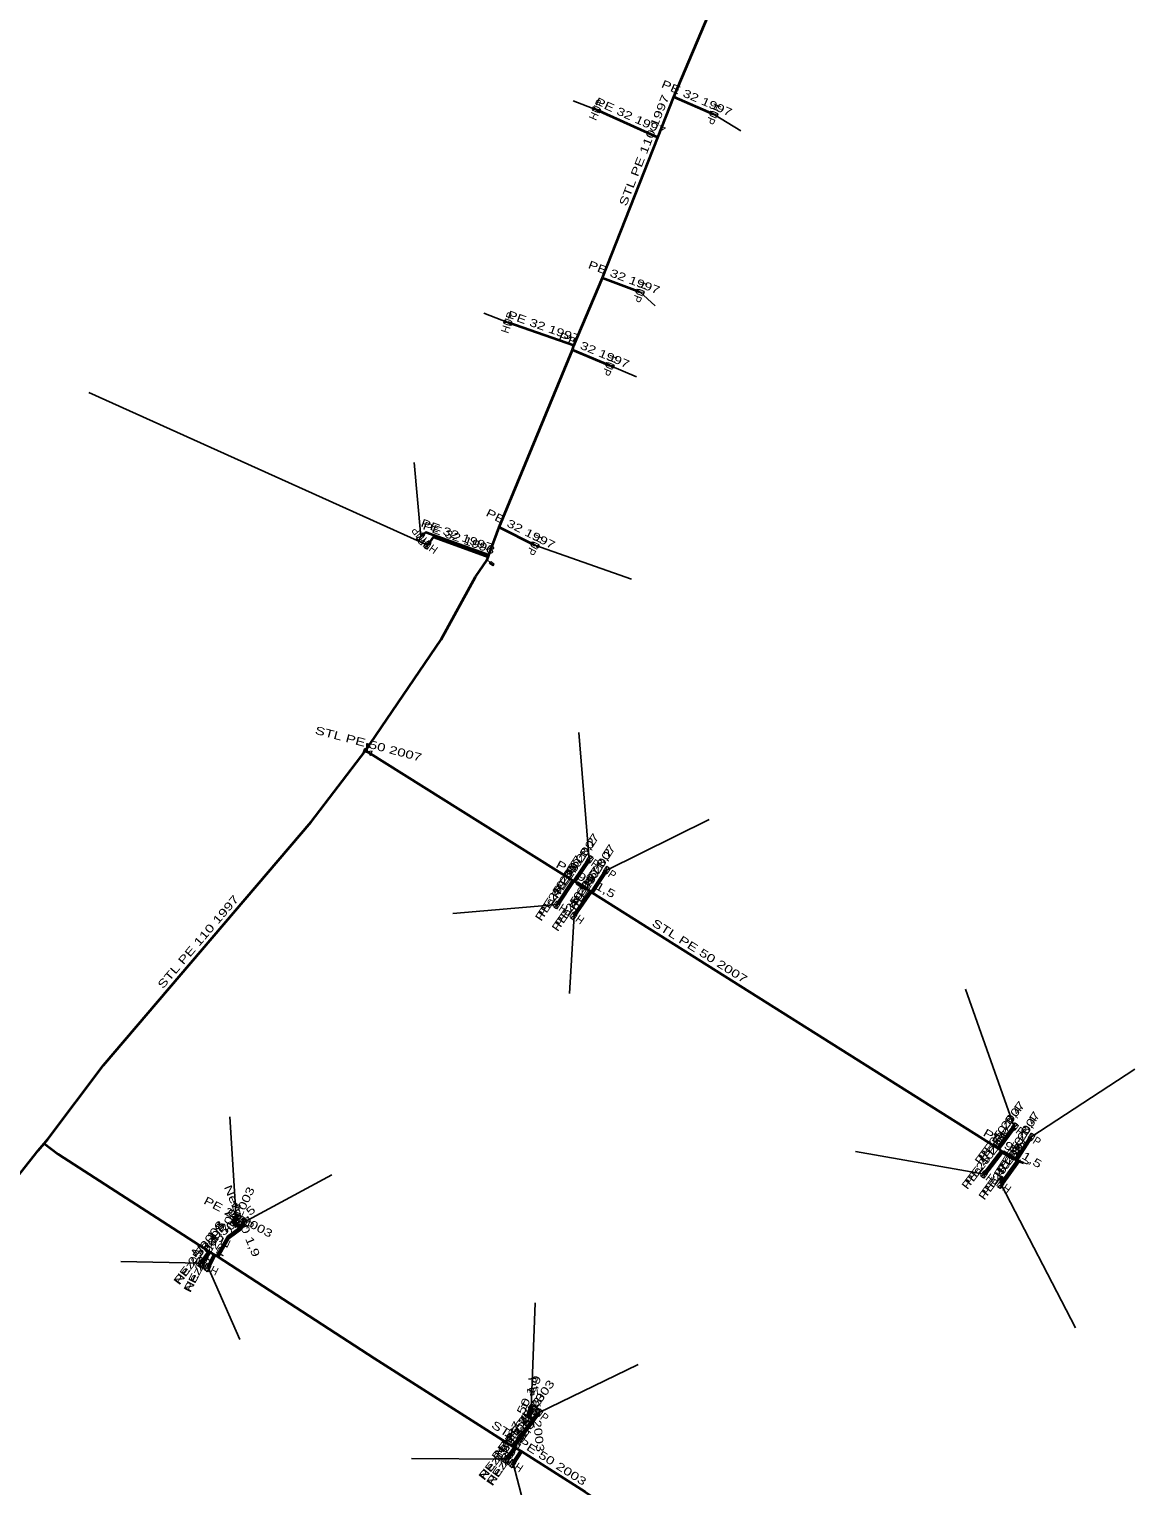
# Model space of a CAD drawing. Extents: x -737484 to -734496, y -1033882 to -1030666.
# Drawn here: x -736166.9 to -736028.6, y -1032786.1 to -1032604 of the extents above; entities that cross this region are included whole.
import ezdxf
from ezdxf.enums import TextEntityAlignment as Align

# ---------------------------------------------------------------- set-up
doc = ezdxf.new("R2010")
doc.units = 0
doc.header["$LTSCALE"] = 0.4
for name, color, linetype, lineweight in [('1', 7, 'Continuous', 13), ('18', 7, 'Continuous', 60), ('22', 7, 'Continuous', 25), ('5', 7, 'Continuous', 35), ('7', 7, 'Continuous', 35)]:
    doc.layers.add(name, color=color, linetype=linetype, lineweight=lineweight)
doc.layers.add('2', color=7, linetype='Continuous')

msp = doc.modelspace()

# ---------------------------------------------------------------- linework, layer by layer
at = {"layer": '1'}
for p, q in [((-736109.567, -1032670.34), (-736109.178, -1032670.654)), ((-736109.167, -1032670.76), (-736108.895, -1032670.98)), ((-736124.522, -1032694.331), (-736124.522, -1032693.831)), ((-736124.447, -1032693.756), (-736124.447, -1032693.406)), ((-736045.29, -1032748.4), (-736045.29, -1032747.9)), ((-736045.215, -1032747.825), (-736045.215, -1032747.475))]:
    msp.add_line(p, q, dxfattribs=at)
for points in [[(-736096.417, -1032614.046), (-736096.254, -1032613.68), (-736095.503, -1032614.453), (-736095.34, -1032614.087)], [(-736080.709, -1032614.621), (-736080.865, -1032614.989), (-736081.63, -1032614.23), (-736081.786, -1032614.598)], [(-736089.92, -1032636.839), (-736090.063, -1032637.212), (-736090.854, -1032636.481), (-736090.997, -1032636.854)], [(-736107.505, -1032640.703), (-736107.375, -1032640.325), (-736106.56, -1032641.028), (-736106.43, -1032640.65)], [(-736093.71, -1032646.04), (-736093.866, -1032646.408), (-736094.631, -1032645.649), (-736094.787, -1032646.017)], [(-736118.144, -1032667.894), (-736118.401, -1032667.588), (-736117.378, -1032667.251), (-736117.635, -1032666.945)], [(-736117.142, -1032669.008), (-736117.47, -1032668.778), (-736116.569, -1032668.189), (-736116.897, -1032667.959)], [(-736103.071, -1032668.526), (-736103.253, -1032668.883), (-736103.962, -1032668.072), (-736104.144, -1032668.429)], [(-736108.789, -1032670.969), (-736108.884, -1032671.085), (-736109.272, -1032670.771), (-736109.178, -1032670.654)], [(-736108.842, -1032670.974), (-736108.889, -1032671.032), (-736109.22, -1032670.764), (-736109.172, -1032670.706)], [(-736108.789, -1032670.969), (-736108.695, -1032670.852), (-736109.084, -1032670.538), (-736109.178, -1032670.654)], [(-736125.1, -1032694.406), (-736124.86, -1032693.856), (-736124.183, -1032694.805), (-736123.943, -1032694.255)], [(-736124.522, -1032693.331), (-736124.672, -1032693.331), (-736124.672, -1032693.831), (-736124.522, -1032693.831)], [(-736124.522, -1032693.331), (-736124.372, -1032693.331), (-736124.372, -1032693.831), (-736124.522, -1032693.831)], [(-736124.485, -1032693.369), (-736124.41, -1032693.369), (-736124.41, -1032693.794), (-736124.485, -1032693.794)], [(-736096.701, -1032707.276), (-736096.369, -1032707.5), (-736097.26, -1032708.105), (-736096.928, -1032708.329)], [(-736094.591, -1032708.635), (-736094.255, -1032708.853), (-736095.136, -1032709.474), (-736094.8, -1032709.692)], [(-736100.895, -1032713.952), (-736101.231, -1032713.734), (-736100.35, -1032713.113), (-736100.686, -1032712.895)], [(-736098.815, -1032715.309), (-736099.143, -1032715.079), (-736098.242, -1032714.49), (-736098.57, -1032714.26)], [(-736043.516, -1032740.693), (-736043.197, -1032740.934), (-736044.118, -1032741.491), (-736043.799, -1032741.732)], [(-736041.483, -1032741.979), (-736041.144, -1032742.191), (-736042.013, -1032742.828), (-736041.674, -1032743.04)], [(-736047.496, -1032747.626), (-736047.815, -1032747.385), (-736046.894, -1032746.828), (-736047.213, -1032746.587)], [(-736045.422, -1032748.922), (-736045.745, -1032748.686), (-736044.834, -1032748.113), (-736045.157, -1032747.877)], [(-736045.29, -1032747.4), (-736045.44, -1032747.4), (-736045.44, -1032747.9), (-736045.29, -1032747.9)], [(-736045.29, -1032747.4), (-736045.14, -1032747.4), (-736045.14, -1032747.9), (-736045.29, -1032747.9)], [(-736045.253, -1032747.438), (-736045.178, -1032747.438), (-736045.178, -1032747.863), (-736045.253, -1032747.863)], [(-736140.814, -1032752.067), (-736140.499, -1032752.314), (-736141.43, -1032752.855), (-736141.115, -1032753.102)], [(-736140.005, -1032752.641), (-736139.643, -1032752.81), (-736140.428, -1032753.547), (-736140.066, -1032753.716)], [(-736145.498, -1032758.762), (-736145.817, -1032758.521), (-736144.896, -1032757.964), (-736145.215, -1032757.723)], [(-736144.529, -1032759.32), (-736144.886, -1032759.138), (-736144.075, -1032758.429), (-736144.432, -1032758.247)], [(-736103.975, -1032775.863), (-736103.628, -1032776.063), (-736104.475, -1032776.73), (-736104.128, -1032776.93)], [(-736103.005, -1032776.448), (-736102.682, -1032776.684), (-736103.593, -1032777.257), (-736103.27, -1032777.493)], [(-736107.324, -1032783.257), (-736107.639, -1032783.01), (-736106.708, -1032782.469), (-736107.023, -1032782.222)], [(-736106.453, -1032783.807), (-736106.785, -1032783.583), (-736105.894, -1032782.978), (-736106.226, -1032782.754)]]:
    msp.add_lwpolyline(points, close=True, dxfattribs=at)
msp.add_lwpolyline([(-736041.927, -1032745.636), (-736042.013, -1032745.871), (-736042.952, -1032745.528), (-736042.867, -1032745.294)], dxfattribs=at)
at = {"layer": '18'}
for p, q in [((-736098.655, -1032710.503), (-736096.815, -1032707.803)), ((-736098.816, -1032710.434), (-736100.791, -1032713.424)), ((-736096.462, -1032711.924), (-736094.696, -1032709.164)), ((-736096.615, -1032711.8), (-736098.693, -1032714.785)), ((-736045.656, -1032743.897), (-736043.658, -1032741.213)), ((-736043.392, -1032745.363), (-736041.579, -1032742.51)), ((-736045.173, -1032744.258), (-736047.355, -1032747.107)), ((-736043.147, -1032745.463), (-736045.29, -1032748.4)), ((-736045.024, -1032744.371), (-736043.707, -1032745.15)), ((-736144.294, -1032756.819), (-736145.356, -1032758.242)), ((-736143.662, -1032757.2), (-736144.481, -1032758.783)), ((-736106.323, -1032781.2), (-736103.137, -1032776.97)), ((-736106.053, -1032781.317), (-736107.173, -1032782.741)), ((-736105.3, -1032781.761), (-736106.339, -1032783.28))]:
    msp.add_line(p, q, dxfattribs=at)
for points in [[(-736098.356, -1032710.709), (-736097.739, -1032711.112), (-736097.057, -1032711.486)], [(-736140.328, -1032753.795), (-736141.137, -1032753.383), (-736141.296, -1032752.997), (-736140.936, -1032752.548)], [(-736143.284, -1032757.398), (-736141.977, -1032755.055), (-736140.402, -1032753.86), (-736140.035, -1032753.179)], [(-736103.801, -1032777.768), (-736104.298, -1032777.483), (-736104.414, -1032777.134), (-736103.982, -1032776.254)]]:
    msp.add_lwpolyline(points, dxfattribs=at)
at = {"layer": '22'}
for p, q in [((-736095.879, -1032614.068), (-736098.835, -1032612.937)), ((-736081.249, -1032614.61), (-736077.847, -1032616.722)), ((-736090.459, -1032636.848), (-736088.549, -1032638.576)), ((-736106.969, -1032640.678), (-736109.996, -1032639.493)), ((-736094.25, -1032646.029), (-736090.914, -1032647.448)), ((-736117.02, -1032668.484), (-736159.393, -1032649.411)), ((-736117.89, -1032667.42), (-736118.694, -1032658.15)), ((-736103.609, -1032668.479), (-736091.505, -1032672.733)), ((-736096.815, -1032707.803), (-736098.127, -1032691.919)), ((-736094.696, -1032709.164), (-736081.81, -1032702.797)), ((-736100.791, -1032713.424), (-736113.871, -1032714.534)), ((-736098.693, -1032714.785), (-736099.272, -1032724.553)), ((-736043.658, -1032741.213), (-736049.748, -1032723.98)), ((-736041.579, -1032742.51), (-736028.564, -1032734)), ((-736140.965, -1032752.585), (-736141.74, -1032739.974)), ((-736047.355, -1032747.107), (-736063.489, -1032744.305)), ((-736140.036, -1032753.179), (-736128.99, -1032747.189)), ((-736045.29, -1032748.4), (-736036.007, -1032766.348)), ((-736145.357, -1032758.243), (-736155.38, -1032758.046)), ((-736144.481, -1032758.784), (-736140.494, -1032767.779)), ((-736104.052, -1032776.397), (-736103.566, -1032763.199)), ((-736103.138, -1032776.971), (-736090.684, -1032770.928)), ((-736107.174, -1032782.74), (-736119.024, -1032782.665)), ((-736106.34, -1032783.281), (-736103.566, -1032793.829))]:
    msp.add_line(p, q, dxfattribs=at)
at = {"layer": '5'}
msp.add_line((-736124.815, -1032694.254), (-736124.522, -1032694.331), dxfattribs=at)
for points in [[(-736124.815, -1032694.254), (-736115.32, -1032680.29), (-736111.02, -1032672.47), (-736109.57, -1032670.34), (-736109.44, -1032669.98), (-736109.36, -1032669.76), (-736108.07, -1032666.23), (-736098.91, -1032644.08), (-736098.72, -1032643.55), (-736095.14, -1032635.08), (-736088.23, -1032617.52), (-736086.24, -1032612.47), (-736081.39, -1032601.03), (-736081.15, -1032600.32), (-736076.37, -1032589.26), (-736075.69, -1032587.6), (-736070.52, -1032575.85), (-736066.71, -1032567.15), (-736058.44, -1032548.57), (-736056.26, -1032543.42), (-736056.11, -1032543.06)], [(-736164.978, -1032743.294), (-736164.512, -1032742.749), (-736157.56, -1032733.51), (-736131.6, -1032703.07), (-736124.815, -1032694.254)], [(-736124.522, -1032694.331), (-736098.816, -1032710.434), (-736098.655, -1032710.503), (-736098.356, -1032710.709), (-736097.739, -1032711.112), (-736097.057, -1032711.486), (-736096.615, -1032711.8), (-736096.462, -1032711.924), (-736045.656, -1032743.897), (-736045.173, -1032744.258), (-736045.024, -1032744.371), (-736043.707, -1032745.15), (-736043.392, -1032745.363), (-736043.147, -1032745.463), (-736042.483, -1032745.7)], [(-736210.44, -1032798.17), (-736209.51, -1032797.02), (-736177.54, -1032759.07), (-736165.735, -1032744.144), (-736164.978, -1032743.294)], [(-736164.978, -1032743.294), (-736163.22, -1032744.622), (-736144.295, -1032756.82), (-736143.663, -1032757.201), (-736143.285, -1032757.399), (-736123.669, -1032770.149), (-736106.324, -1032781.201), (-736106.054, -1032781.318), (-736105.301, -1032781.762), (-736097.333, -1032786.842), (-736084.708, -1032795.224), (-736075.443, -1032801.061), (-736071.322, -1032803.858), (-736070.031, -1032804.587), (-736068.124, -1032805.517), (-736067.175, -1032806.115), (-736055.501, -1032813.666), (-736043.698, -1032820.973), (-736041.939, -1032821.797)]]:
    msp.add_lwpolyline(points, dxfattribs=at)
at = {"layer": '7'}
for p, q in [((-736086.24, -1032612.47), (-736081.248, -1032614.61)), ((-736088.23, -1032617.52), (-736095.879, -1032614.067)), ((-736095.14, -1032635.08), (-736090.459, -1032636.847)), ((-736098.72, -1032643.55), (-736106.968, -1032640.677)), ((-736098.91, -1032644.08), (-736094.249, -1032646.029)), ((-736108.07, -1032666.23), (-736103.608, -1032668.478)), ((-736098.655, -1032710.503), (-736096.815, -1032707.803)), ((-736098.816, -1032710.434), (-736100.791, -1032713.424)), ((-736096.462, -1032711.924), (-736094.696, -1032709.164)), ((-736096.615, -1032711.8), (-736098.693, -1032714.785)), ((-736045.656, -1032743.897), (-736043.658, -1032741.213)), ((-736043.392, -1032745.363), (-736041.579, -1032742.51)), ((-736045.173, -1032744.258), (-736047.355, -1032747.107)), ((-736043.147, -1032745.463), (-736045.29, -1032748.4)), ((-736140.328, -1032753.796), (-736140.036, -1032753.179)), ((-736144.295, -1032756.82), (-736145.357, -1032758.243)), ((-736143.663, -1032757.201), (-736144.481, -1032758.784)), ((-736106.324, -1032781.201), (-736103.776, -1032777.844)), ((-736103.776, -1032777.844), (-736103.138, -1032776.971)), ((-736106.054, -1032781.318), (-736107.174, -1032782.74)), ((-736105.301, -1032781.762), (-736106.34, -1032783.281))]:
    msp.add_line(p, q, dxfattribs=at)
for points in [[(-736109.36, -1032669.76), (-736117.26, -1032666.9), (-736117.89, -1032667.42)], [(-736109.44, -1032669.98), (-736116.32, -1032667.5), (-736117.02, -1032668.484)], [(-736140.328, -1032753.796), (-736141.189, -1032753.351), (-736141.307, -1032753.03), (-736140.965, -1032752.585)], [(-736143.285, -1032757.399), (-736141.98, -1032755.075), (-736140.328, -1032753.796)], [(-736103.776, -1032777.844), (-736104.39, -1032777.528), (-736104.442, -1032777.074), (-736104.052, -1032776.397)]]:
    msp.add_lwpolyline(points, dxfattribs=at)

# ---------------------------------------------------------------- texts
at = {"layer": '18', "width": 1.4}
for s, rotation, p in [('PE 40 3,2', 55.726, (-736098.1477, -1032708.8711)), ('PE 40 3,2', 57.387, (-736096.0002, -1032710.274)), ('PE 40 3,6', 56.554, (-736100.2204, -1032711.6526)), ('PE 90 1,5', 331.26, (-736097.4799, -1032710.6831)), ('PE 40 3,6', 55.156, (-736098.0637, -1032713.0067)), ('PE 40 3,4', 53.336, (-736045.0573, -1032742.2561)), ('PE 40 3,4', 57.565, (-736042.9071, -1032743.6682)), ('PE 40 3,6', 52.552, (-736046.6608, -1032745.378)), ('PE 90 1,5', 329.396, (-736044.1106, -1032744.3296)), ('PE 40 3,6', 53.883, (-736044.6219, -1032746.6362)), ('Nez. 50 1,9', 292.388, (-736140.6902, -1032753.1531)), ('Nez. 50 5,5', 37.189, (-736142.2517, -1032754.6355)), ('Nez. 50 1,8', 53.266, (-736145.2251, -1032757.2306)), ('Nez. 50 1,8', 62.644, (-736144.5149, -1032757.7613)), ('Nez. 50 1,9', 63.853, (-736104.8536, -1032776.8958)), ('Nez. 50 5,3', 53.013, (-736105.1296, -1032778.7838)), ('Nez. 50 1,8', 51.814, (-736107.0056, -1032781.7191)), ('Nez. 50 1,8', 55.628, (-736106.2318, -1032782.2378))]:
    msp.add_text(s, height=1, rotation=rotation, dxfattribs=at).set_placement(p, align=Align.CENTER)
at = {"layer": '2', "width": 0.95}
for rotation, p in [(66, (-736095.4213, -1032614.2699)), (247, (-736081.7073, -1032614.4141)), (249, (-736090.9253, -1032636.6673)), (71, (-736106.495, -1032640.8393)), (247, (-736094.7083, -1032645.8331)), (130, (-736117.5066, -1032667.0979)), (243, (-736104.0535, -1032668.2505)), (145, (-736116.7327, -1032668.0741)), (326, (-736097.0941, -1032708.2169)), (327, (-736094.9678, -1032709.5829)), (147, (-736100.5182, -1032713.0041)), (145, (-736098.4057, -1032714.3751)), (323, (-736043.9584, -1032741.6115)), (328, (-736041.8435, -1032742.9333)), (143, (-736047.0536, -1032746.7075)), (144, (-736044.9956, -1032747.995)), (322, (-736141.2723, -1032752.979)), (335, (-736140.2468, -1032753.6316)), (143, (-736145.0556, -1032757.8435)), (153, (-736144.2535, -1032758.3375)), (330, (-736104.3015, -1032776.8291)), (324, (-736103.4314, -1032777.375)), (142, (-736106.8657, -1032782.345)), (146, (-736106.0599, -1032782.8661))]:
    msp.add_text('HUP', height=1, rotation=rotation, dxfattribs=at).set_placement(p, align=Align.CENTER)
at = {"layer": '5', "width": 1.4}
for s, rotation, p in [('STL PE 110 1997', 68.52, (-736089.4746, -1032619.3186)), ('STL PE 50 2007', 345.276, (-736124.5406, -1032693.8081)), ('STL PE 110 1997', 49.542, (-736145.3346, -1032718.4044)), ('STL PE 50 2007', 327.817, (-736083.2568, -1032719.643)), ('STL PE 50 2003', 327.48, (-736103.3563, -1032782.4086))]:
    msp.add_text(s, height=1, rotation=rotation, dxfattribs=at).set_placement(p, align=Align.CENTER)
at = {"layer": '7', "width": 1.35}
for s, rotation, p in [('PE 32 1997', 336.796, (-736083.5465, -1032613.0797)), ('PE 32 1997', 335.704, (-736091.8482, -1032615.3375)), ('PE 32 1997', 339.319, (-736092.6226, -1032635.4947)), ('PE 32 1997', 340.795, (-736102.679, -1032641.6406)), ('PE 32 1997', 337.308, (-736096.3864, -1032644.5924)), ('PE 32 1997', 340.098, (-736113.5237, -1032667.7206)), ('PE 32 1997', 333.261, (-736105.6135, -1032666.9071)), ('PE 32 1998', 340.178, (-736113.2781, -1032668.0645)), ('PE 25 2007', 55.726, (-736098.1473, -1032708.8711)), ('PE 25 2007', 56.554, (-736100.2203, -1032711.6531)), ('PE 25 2007', 57.387, (-736095.9997, -1032710.274)), ('PE 25 2007', 55.156, (-736098.064, -1032713.0062)), ('PE 25 2007', 53.336, (-736045.0574, -1032742.2556)), ('PE 25 2007', 57.565, (-736042.9071, -1032743.6677)), ('PE 25 2007', 52.552, (-736046.66, -1032745.378)), ('PE 25 2007', 53.883, (-736044.6223, -1032746.6362)), ('PE 25 2003', 64.674, (-736140.6332, -1032753.2734)), ('PE 25 2003', 60.684, (-736142.5564, -1032755.0808)), ('PE 25 2003', 332.668, (-736140.9296, -1032752.9215)), ('PE 25 2003', 53.266, (-736145.2257, -1032757.2321)), ('PE 25 2003', 62.673, (-736144.5159, -1032757.7625)), ('PE 25 2003', 276.534, (-736103.9239, -1032777.1986)), ('PE 25 2003', 53.84, (-736103.8601, -1032777.112)), ('PE 25 2003', 52.801, (-736105.4479, -1032779.2198)), ('PE 25 2003', 51.775, (-736107.0066, -1032781.7189)), ('PE 25 2003', 55.628, (-736106.2325, -1032782.2388))]:
    msp.add_text(s, height=1, rotation=rotation, dxfattribs=at).set_placement(p, align=Align.CENTER)

doc.saveas('drawing.dxf')
